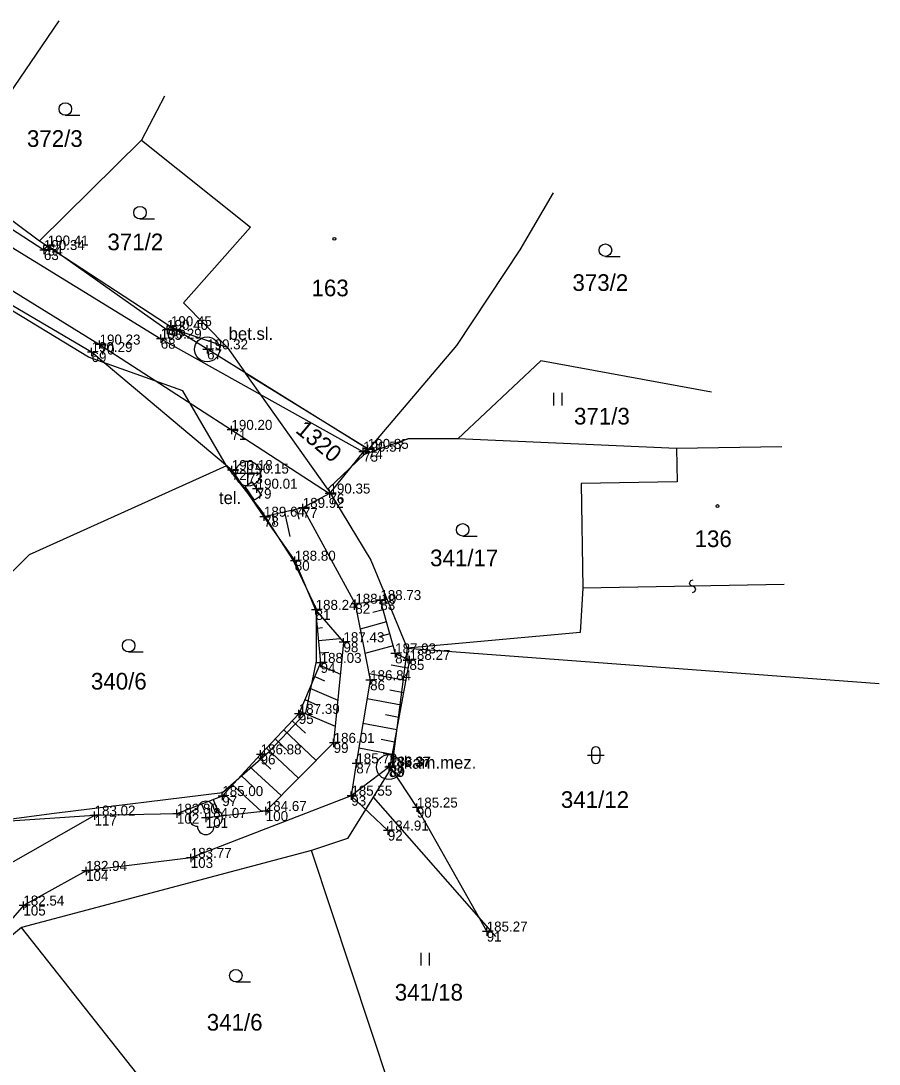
# Model space of a CAD drawing. Extents: x -744860 to -744734, y -966759 to -966608.
# Drawn here: x -744785.6 to -744734.1, y -966693.6 to -966631 of the extents above; entities that cross this region are included whole.
import ezdxf

# ---------------------------------------------------------------- set-up
doc = ezdxf.new("R2010")
doc.units = 0
for name, color, linetype in [('Bod polohopisu - výška', 7, 'Continuous'), ('Bod polohopisu - značka', 7, 'Continuous'), ('Bod polohopisu - číslo', 7, 'Continuous'), ('Doplňkové značky', 7, 'Continuous'), ('KM', 7, 'Continuous'), ('Ploty_opěrné zdi', 7, 'Continuous'), ('Popisy objektů_povrchů', 7, 'Continuous'), ('Rozhraní ploch', 7, 'Continuous'), ('Stromy_porost', 7, 'Continuous'), ('Vstup na pozemek', 7, 'Continuous'), ('Výškopis', 7, 'Continuous'), ('Značky IS', 7, 'Continuous')]:
    doc.layers.add(name, color=color, linetype=linetype)

msp = doc.modelspace()

# ---------------------------------------------------------------- linework, layer by layer
at = {"layer": 'Bod polohopisu - značka'}
for p, q in [((-744783.99, -966644.45), (-744784.24, -966644.45)), ((-744784.22, -966644.72), (-744784.22, -966644.47)), ((-744783.99, -966644.45), (-744783.99, -966644.2)), ((-744783.99, -966644.45), (-744783.74, -966644.45)), ((-744783.99, -966644.45), (-744783.99, -966644.7)), ((-744784.22, -966644.72), (-744784.47, -966644.72)), ((-744784.22, -966644.72), (-744783.97, -966644.72)), ((-744784.22, -966644.72), (-744784.22, -966644.97)), ((-744776.6, -966649.29), (-744776.85, -966649.29)), ((-744776.83, -966649.51), (-744776.83, -966649.26)), ((-744776.6, -966649.29), (-744776.6, -966649.04)), ((-744776.6, -966649.29), (-744776.35, -966649.29)), ((-744776.6, -966649.29), (-744776.6, -966649.54)), ((-744777.21, -966650.04), (-744777.46, -966650.04)), ((-744777.21, -966650.04), (-744777.21, -966649.79)), ((-744777.21, -966650.04), (-744776.96, -966650.04)), ((-744777.21, -966650.04), (-744777.21, -966650.29)), ((-744776.83, -966649.51), (-744777.08, -966649.51)), ((-744776.83, -966649.51), (-744776.58, -966649.51)), ((-744776.83, -966649.51), (-744776.83, -966649.76)), ((-744781.36, -966650.84), (-744781.36, -966650.59)), ((-744780.88, -966650.39), (-744781.13, -966650.39)), ((-744780.88, -966650.39), (-744780.88, -966650.14)), ((-744780.88, -966650.39), (-744780.63, -966650.39)), ((-744780.88, -966650.39), (-744780.88, -966650.64)), ((-744774.43, -966650.68), (-744774.68, -966650.68)), ((-744774.43, -966650.68), (-744774.43, -966650.43)), ((-744774.43, -966650.68), (-744774.18, -966650.68)), ((-744774.43, -966650.68), (-744774.43, -966650.93)), ((-744781.36, -966650.84), (-744781.61, -966650.84)), ((-744781.36, -966650.84), (-744781.11, -966650.84)), ((-744781.36, -966650.84), (-744781.36, -966651.09)), ((-744772.97, -966655.51), (-744773.22, -966655.51)), ((-744772.97, -966655.51), (-744772.97, -966655.26)), ((-744772.97, -966655.51), (-744772.72, -966655.51)), ((-744772.97, -966655.51), (-744772.97, -966655.76)), ((-744765.07, -966656.82), (-744765.32, -966656.82)), ((-744765.07, -966656.82), (-744765.07, -966656.57)), ((-744765.07, -966656.82), (-744764.82, -966656.82)), ((-744765.07, -966656.82), (-744765.07, -966657.07)), ((-744764.79, -966656.65), (-744765.04, -966656.65)), ((-744764.79, -966656.65), (-744764.79, -966656.4)), ((-744764.79, -966656.65), (-744764.54, -966656.65)), ((-744764.79, -966656.65), (-744764.79, -966656.9)), ((-744772.95, -966657.92), (-744773.2, -966657.92)), ((-744772.95, -966657.92), (-744772.95, -966657.67)), ((-744772.95, -966657.92), (-744772.7, -966657.92)), ((-744772.95, -966657.92), (-744772.95, -966658.17)), ((-744771.98, -966658.13), (-744772.23, -966658.13)), ((-744771.98, -966658.13), (-744771.98, -966657.88)), ((-744771.98, -966658.13), (-744771.73, -966658.13)), ((-744771.98, -966658.13), (-744771.98, -966658.38)), ((-744771.46, -966659.04), (-744771.46, -966658.79)), ((-744771.46, -966659.04), (-744771.71, -966659.04)), ((-744771.46, -966659.04), (-744771.21, -966659.04)), ((-744771.46, -966659.04), (-744771.46, -966659.29)), ((-744767.09, -966659.33), (-744767.34, -966659.33)), ((-744767.09, -966659.33), (-744767.09, -966659.08)), ((-744767.09, -966659.33), (-744766.84, -966659.33)), ((-744767.09, -966659.33), (-744767.09, -966659.58)), ((-744768.69, -966660.19), (-744768.69, -966659.94)), ((-744771.02, -966660.72), (-744771.27, -966660.72)), ((-744771.02, -966660.72), (-744771.02, -966660.47)), ((-744771.02, -966660.72), (-744770.77, -966660.72)), ((-744771.02, -966660.72), (-744771.02, -966660.97)), ((-744768.69, -966660.19), (-744768.94, -966660.19)), ((-744768.69, -966660.19), (-744768.44, -966660.19)), ((-744768.69, -966660.19), (-744768.69, -966660.44)), ((-744769.17, -966663.36), (-744769.17, -966663.11)), ((-744769.17, -966663.36), (-744769.42, -966663.36)), ((-744769.17, -966663.36), (-744768.92, -966663.36)), ((-744769.17, -966663.36), (-744769.17, -966663.61)), ((-744765.54, -966665.94), (-744765.54, -966665.69)), ((-744764.04, -966665.72), (-744764.29, -966665.72)), ((-744764.04, -966665.72), (-744764.04, -966665.47)), ((-744764.04, -966665.72), (-744763.79, -966665.72)), ((-744764.04, -966665.72), (-744764.04, -966665.97)), ((-744767.92, -966666.31), (-744768.17, -966666.31)), ((-744767.92, -966666.31), (-744767.92, -966666.06)), ((-744767.92, -966666.31), (-744767.67, -966666.31)), ((-744767.92, -966666.31), (-744767.92, -966666.56)), ((-744765.54, -966665.94), (-744765.79, -966665.94)), ((-744765.54, -966665.94), (-744765.29, -966665.94)), ((-744765.54, -966665.94), (-744765.54, -966666.19)), ((-744766.25, -966668.25), (-744766.5, -966668.25)), ((-744766.25, -966668.25), (-744766.25, -966668)), ((-744766.25, -966668.25), (-744766, -966668.25)), ((-744766.25, -966668.25), (-744766.25, -966668.5)), ((-744763.15, -966668.92), (-744763.15, -966668.67)), ((-744767.62, -966669.49), (-744767.87, -966669.49)), ((-744767.62, -966669.49), (-744767.62, -966669.24)), ((-744767.62, -966669.49), (-744767.37, -966669.49)), ((-744767.62, -966669.49), (-744767.62, -966669.74)), ((-744763.15, -966668.92), (-744763.4, -966668.92)), ((-744763.15, -966668.92), (-744762.9, -966668.92)), ((-744763.15, -966668.92), (-744763.15, -966669.17)), ((-744762.29, -966669.31), (-744762.54, -966669.31)), ((-744762.29, -966669.31), (-744762.29, -966669.06)), ((-744762.29, -966669.31), (-744762.04, -966669.31)), ((-744762.29, -966669.31), (-744762.29, -966669.56)), ((-744764.65, -966670.53), (-744764.9, -966670.53)), ((-744764.65, -966670.53), (-744764.65, -966670.28)), ((-744764.65, -966670.53), (-744764.4, -966670.53)), ((-744764.65, -966670.53), (-744764.65, -966670.78)), ((-744768.93, -966672.55), (-744769.18, -966672.55)), ((-744768.93, -966672.55), (-744768.93, -966672.3)), ((-744768.93, -966672.55), (-744768.68, -966672.55)), ((-744768.93, -966672.55), (-744768.93, -966672.8)), ((-744766.84, -966674.29), (-744767.09, -966674.29)), ((-744766.84, -966674.29), (-744766.84, -966674.04)), ((-744766.84, -966674.29), (-744766.59, -966674.29)), ((-744766.84, -966674.29), (-744766.84, -966674.54)), ((-744771.22, -966674.98), (-744771.47, -966674.98)), ((-744771.22, -966674.98), (-744771.22, -966674.73)), ((-744771.22, -966674.98), (-744770.97, -966674.98)), ((-744771.22, -966674.98), (-744771.22, -966675.23)), ((-744765.48, -966675.52), (-744765.73, -966675.52)), ((-744765.48, -966675.52), (-744765.48, -966675.27)), ((-744765.48, -966675.52), (-744765.23, -966675.52)), ((-744765.48, -966675.52), (-744765.48, -966675.77)), ((-744763.52, -966675.74), (-744763.77, -966675.74)), ((-744763.46, -966675.71), (-744763.71, -966675.71)), ((-744763.52, -966675.74), (-744763.52, -966675.49)), ((-744763.52, -966675.74), (-744763.27, -966675.74)), ((-744763.52, -966675.74), (-744763.52, -966675.99)), ((-744763.46, -966675.71), (-744763.46, -966675.46)), ((-744763.46, -966675.71), (-744763.21, -966675.71)), ((-744763.46, -966675.71), (-744763.46, -966675.96)), ((-744773.52, -966677.48), (-744773.77, -966677.48)), ((-744773.52, -966677.48), (-744773.52, -966677.23)), ((-744773.52, -966677.48), (-744773.27, -966677.48)), ((-744773.52, -966677.48), (-744773.52, -966677.73)), ((-744765.78, -966677.46), (-744766.03, -966677.46)), ((-744765.78, -966677.46), (-744765.78, -966677.21)), ((-744765.78, -966677.46), (-744765.53, -966677.46)), ((-744765.78, -966677.46), (-744765.78, -966677.71)), ((-744770.91, -966678.38), (-744770.91, -966678.13)), ((-744761.85, -966678.17), (-744762.1, -966678.17)), ((-744761.85, -966678.17), (-744761.85, -966677.92)), ((-744761.85, -966678.17), (-744761.6, -966678.17)), ((-744761.85, -966678.17), (-744761.85, -966678.42)), ((-744781.18, -966678.65), (-744781.43, -966678.65)), ((-744781.18, -966678.65), (-744781.18, -966678.4)), ((-744781.18, -966678.65), (-744780.93, -966678.65)), ((-744781.18, -966678.65), (-744781.18, -966678.9)), ((-744776.24, -966678.54), (-744776.49, -966678.54)), ((-744776.24, -966678.54), (-744776.24, -966678.29)), ((-744776.24, -966678.54), (-744775.99, -966678.54)), ((-744776.24, -966678.54), (-744776.24, -966678.79)), ((-744774.51, -966678.79), (-744774.76, -966678.79)), ((-744774.51, -966678.79), (-744774.51, -966678.54)), ((-744774.51, -966678.79), (-744774.26, -966678.79)), ((-744774.51, -966678.79), (-744774.51, -966679.04)), ((-744770.91, -966678.38), (-744771.16, -966678.38)), ((-744770.91, -966678.38), (-744770.66, -966678.38)), ((-744770.91, -966678.38), (-744770.91, -966678.63)), ((-744763.59, -966679.55), (-744763.59, -966679.3)), ((-744763.59, -966679.55), (-744763.84, -966679.55)), ((-744763.59, -966679.55), (-744763.34, -966679.55)), ((-744763.59, -966679.55), (-744763.59, -966679.8)), ((-744775.41, -966681.19), (-744775.66, -966681.19)), ((-744775.41, -966681.19), (-744775.41, -966680.94)), ((-744775.41, -966681.19), (-744775.16, -966681.19)), ((-744775.41, -966681.19), (-744775.41, -966681.44)), ((-744781.69, -966681.97), (-744781.94, -966681.97)), ((-744781.69, -966681.97), (-744781.69, -966681.72)), ((-744781.69, -966681.97), (-744781.44, -966681.97)), ((-744781.69, -966681.97), (-744781.69, -966682.22)), ((-744785.45, -966684.05), (-744785.45, -966683.8)), ((-744785.45, -966684.05), (-744785.7, -966684.05)), ((-744785.45, -966684.05), (-744785.2, -966684.05)), ((-744785.45, -966684.05), (-744785.45, -966684.3)), ((-744757.66, -966685.61), (-744757.91, -966685.61)), ((-744757.66, -966685.61), (-744757.66, -966685.36)), ((-744757.66, -966685.61), (-744757.41, -966685.61)), ((-744757.66, -966685.61), (-744757.66, -966685.86))]:
    msp.add_line(p, q, dxfattribs=at)
at = {"layer": 'Doplňkové značky'}
for centre in [(-744774.43, -966650.68), (-744763.52, -966675.74)]:
    msp.add_circle(centre, 0.75, dxfattribs=at)
at = {"layer": 'KM'}
for p, q in [((-744789.67, -966640.3), (-744783.3, -966630.97)), ((-744782.937, -966636.63), (-744782.062, -966636.63)), ((-744778.37, -966638.12), (-744784.48, -966644.17)), ((-744789.67, -966640.3), (-744784.48, -966644.17)), ((-744778.456, -966642.85), (-744777.581, -966642.85)), ((-744750.538, -966645.102), (-744749.663, -966645.102)), ((-744781.55, -966651.15), (-744788.18, -966647.11)), ((-744773.22, -966650.55), (-744772.12, -966652.1)), ((-744764.73, -966656.66), (-744759.45, -966650.45)), ((-744754.42, -966651.36), (-744759.4, -966656.05)), ((-744744.18, -966653.24), (-744754.42, -966651.36)), ((-744767.18, -966659.06), (-744772.12, -966652.1)), ((-744772.12, -966652.1), (-744764.73, -966656.66)), ((-744753.635, -966654.047), (-744753.635, -966653.297)), ((-744753.135, -966654.047), (-744753.135, -966653.297)), ((-744746.27, -966656.63), (-744759.4, -966656.05)), ((-744765.01, -966656.99), (-744767.18, -966659.06)), ((-744764.73, -966656.66), (-744765.01, -966656.99)), ((-744759.096, -966661.88), (-744758.221, -966661.88)), ((-744739.809, -966664.794), (-744751.89, -966665)), ((-744779.137, -966668.83), (-744778.262, -966668.83)), ((-744762.42, -966668.6), (-744734.12, -966670.73)), ((-744751.613, -966675.017), (-744750.612, -966675.017)), ((-744751.363, -966674.767), (-744751.363, -966675.267)), ((-744750.862, -966675.267), (-744750.862, -966674.767)), ((-744764.47, -966677.55), (-744757.14, -966685.91)), ((-744768.17, -966680.74), (-744785.56, -966685.37)), ((-744760.83, -966702.86), (-744768.17, -966680.74)), ((-744771, -966703.8), (-744785.56, -966685.37)), ((-744761.594, -966687.637), (-744761.594, -966686.887)), ((-744761.093, -966687.637), (-744761.093, -966686.887)), ((-744772.707, -966688.628), (-744771.832, -966688.628))]:
    msp.add_line(p, q, dxfattribs=at)
for points in [[(-744776.99, -966635.48), (-744778.37, -966638.12)], [(-744778.37, -966638.12), (-744771.83, -966643.35), (-744775.85, -966647.89), (-744773.22, -966650.55)], [(-744759.45, -966650.45), (-744755.66, -966644.71), (-744753.65, -966641.28)], [(-744784.48, -966644.17), (-744776.34, -966649.49), (-744773.22, -966650.55)], [(-744773.26, -966657.67), (-744775.88, -966653.17), (-744781.55, -966651.15)], [(-744759.4, -966656.05), (-744762.36, -966656.04), (-744765.01, -966656.99)], [(-744746.27, -966656.63), (-744746.23, -966658.62), (-744752, -966658.72), (-744751.89, -966665), (-744752.05, -966667.67), (-744762.42, -966668.6)], [(-744739.95, -966656.52), (-744746.27, -966656.63)], [(-744773.26, -966657.67), (-744785.1, -966663), (-744789.495, -966667.418)], [(-744787.69, -966679.04), (-744783.61, -966678.5), (-744773.51, -966677.27), (-744770.7, -966674.8), (-744768.5, -966672.49), (-744767.87, -966669.38), (-744767.86, -966666.26), (-744769.28, -966663.29), (-744771.19, -966660.32), (-744773.26, -966657.67)], [(-744767.18, -966659.06), (-744764.6, -966663.33), (-744762.42, -966668.6)], [(-744745.319, -966665.263), (-744745.17, -966665.211), (-744745.113, -966665.055), (-744745.185, -966664.921), (-744745.427, -966664.84), (-744745.489, -966664.701), (-744745.422, -966664.555), (-744745.282, -966664.512)], [(-744762.42, -966668.6), (-744763.34, -966675.72), (-744764.47, -966677.55)], [(-744764.47, -966677.55), (-744766, -966680.03), (-744768.17, -966680.74)], [(-744785.56, -966685.37), (-744792.95, -966691.5), (-744798.91, -966697.31)]]:
    msp.add_lwpolyline(points, dxfattribs=at)
for centre, radius in [((-744782.936, -966636.255), 0.375), ((-744778.456, -966642.475), 0.375), ((-744766.793, -966644.045), 0.0875), ((-744750.538, -966644.727), 0.375), ((-744743.816, -966660.08), 0.0875), ((-744759.096, -966661.505), 0.375), ((-744779.136, -966668.455), 0.375), ((-744772.707, -966688.253), 0.375)]:
    msp.add_circle(centre, radius, dxfattribs=at)
for centre, start, end in [((-744751.113, -966674.767), 0, 180), ((-744751.113, -966675.267), 180, 359.98789)]:
    msp.add_arc(centre, 0.25, start, end, dxfattribs=at)
at = {"layer": 'Ploty_opěrné zdi'}
for points in [[(-744784.22, -966644.72), (-744789.39, -966641.39), (-744797.95, -966635.69)], [(-744784.22, -966644.72), (-744783.99, -966644.45), (-744776.83, -966649.51), (-744776.6, -966649.29), (-744764.79, -966656.65)], [(-744772.95, -966657.92), (-744781.36, -966650.84), (-744791.49, -966644.91)], [(-744764.79, -966656.65), (-744765.07, -966656.82)], [(-744772.95, -966657.92), (-744771.02, -966660.72), (-744769.17, -966663.36), (-744767.92, -966666.31), (-744767.62, -966669.49), (-744768.93, -966672.55), (-744771.22, -966674.98), (-744773.52, -966677.48), (-744776.24, -966678.54)], [(-744767.09, -966659.33), (-744768.69, -966660.19), (-744765.54, -966665.94), (-744764.04, -966665.72)], [(-744764.04, -966665.72), (-744763.15, -966668.92), (-744762.29, -966669.31)], [(-744762.29, -966669.31), (-744763.46, -966675.71), (-744761.85, -966678.17)], [(-744761.85, -966678.17), (-744757.66, -966685.61)], [(-744776.24, -966678.54), (-744781.18, -966678.65), (-744788.06, -966679.1), (-744794.89, -966683.71)]]:
    msp.add_lwpolyline(points, dxfattribs=at)
at = {"layer": 'Rozhraní ploch'}
for points in [[(-744807.21, -966636.7), (-744806.82, -966636.25), (-744799.04, -966639.39), (-744791.03, -966644.12), (-744780.88, -966650.39), (-744772.97, -966655.51), (-744767.09, -966659.33)], [(-744796.67, -966637.96), (-744789.94, -966642.23), (-744777.21, -966650.04), (-744765.07, -966656.82)]]:
    msp.add_lwpolyline(points, dxfattribs=at)
at = {"layer": 'Stromy_porost'}
for points in [[(-744763.59, -966679.55), (-744765.78, -966677.46), (-744775.41, -966681.19), (-744781.69, -966681.97), (-744785.45, -966684.05), (-744788.92, -966688.06), (-744792.9, -966691.9), (-744797.56, -966696.54), (-744801.48, -966702.05), (-744809.76, -966709.76), (-744814.1, -966714.28), (-744821.74, -966720.14), (-744827.24, -966731.82), (-744829.32, -966738.32), (-744831.32, -966741.72), (-744834.98, -966747.08), (-744831.81, -966750.81), (-744822.41, -966749.82)], [(-744781.18, -966678.65), (-744792.93, -966685.32), (-744796.85, -966689.7), (-744800.79, -966697.66), (-744807.35, -966700.35), (-744816.47, -966709.2)]]:
    msp.add_lwpolyline(points, dxfattribs=at)
msp.add_circle((-744774.51, -966678.79), 0.0005, dxfattribs=at)
for centre, start, end in [((-744774.51, -966678.29), 0, 179.99999), ((-744775.01, -966678.79), 89.99999, 269.99999), ((-744774.01, -966678.79), 270, 89.99999), ((-744774.51, -966679.29), 179.99999, 359.99999)]:
    msp.add_arc(centre, 0.5, start, end, dxfattribs=at)
at = {"layer": 'Vstup na pozemek'}
msp.add_lwpolyline([(-744765.07, -966656.82), (-744767.09, -966659.33)], dxfattribs=at)
at = {"layer": 'Výškopis'}
for points in [[(-744768.69, -966660.19), (-744771.02, -966660.72)], [(-744770.523, -966660.607), (-744770.39, -966661.192)], [(-744769.792, -966660.441), (-744769.459, -966661.903)], [(-744769.061, -966660.274), (-744768.927, -966660.859)], [(-744767.92, -966666.31), (-744766.25, -966668.25), (-744766.84, -966674.29), (-744770.91, -966678.38), (-744774.51, -966678.79)], [(-744765.54, -966665.94), (-744764.65, -966670.53), (-744765.48, -966675.52), (-744765.78, -966677.46)], [(-744763.879, -966666.299), (-744764.483, -966666.467)], [(-744767.817, -966667.398), (-744767.509, -966667.369)], [(-744763.678, -966667.022), (-744765.246, -966667.458)], [(-744767.747, -966668.145), (-744766.446, -966668.022)], [(-744763.477, -966667.744), (-744764.127, -966667.925)], [(-744767.676, -966668.891), (-744767.126, -966668.839)], [(-744763.276, -966668.467), (-744764.959, -966668.935)], [(-744767.678, -966669.627), (-744766.436, -966670.158)], [(-744762.382, -966669.812), (-744763.38, -966669.629)], [(-744767.974, -966670.316), (-744767.389, -966670.566)], [(-744762.517, -966670.549), (-744764.724, -966670.146)], [(-744768.269, -966671.006), (-744766.589, -966671.725)], [(-744762.651, -966671.287), (-744763.476, -966671.136)], [(-744768.564, -966671.695), (-744767.805, -966672.02)], [(-744762.786, -966672.025), (-744764.836, -966671.65)], [(-744768.859, -966672.384), (-744766.742, -966673.291)], [(-744762.921, -966672.763), (-744763.736, -966672.614)], [(-744769.321, -966672.965), (-744768.537, -966673.704)], [(-744763.056, -966673.501), (-744765.082, -966673.13)], [(-744769.835, -966673.511), (-744767.889, -966675.344)], [(-744770.35, -966674.056), (-744769.577, -966674.784)], [(-744763.191, -966674.238), (-744763.997, -966674.091)], [(-744770.864, -966674.602), (-744768.948, -966676.408)], [(-744763.326, -966674.976), (-744765.329, -966674.61)], [(-744771.884, -966675.702), (-744769.984, -966677.45)], [(-744771.376, -966675.15), (-744770.608, -966675.857)], [(-744763.46, -966675.71), (-744765.78, -966677.46)], [(-744772.392, -966676.254), (-744771.641, -966676.945)], [(-744772.9, -966676.806), (-744771.158, -966678.408)], [(-744773.408, -966677.358), (-744772.902, -966677.823)], [(-744774.763, -966677.964), (-744774.635, -966678.292)], [(-744774.064, -966677.692), (-744773.673, -966678.695)]]:
    msp.add_lwpolyline(points, dxfattribs=at)
at = {"layer": 'Značky IS'}
for p, q in [((-744771.981, -966658.878), (-744771.98, -966657.383)), ((-744771.228, -966658.136), (-744772.728, -966658.131))]:
    msp.add_line(p, q, dxfattribs=at)
msp.add_lwpolyline([(-744771.176, -966659.452), (-744771.588, -966659.735), (-744772.155, -966658.912), (-744771.744, -966658.628)], close=True, dxfattribs=at)
msp.add_circle((-744771.98, -966658.13), 0.75, dxfattribs=at)

# ---------------------------------------------------------------- texts
at = {"layer": 'Bod polohopisu - výška'}
for s, p in [('190.41', (-744783.99, -966644.45)), ('190.34', (-744784.22, -966644.72)), ('190.45', (-744776.6, -966649.29)), ('190.29', (-744777.21, -966650.04)), ('190.40', (-744776.83, -966649.51)), ('190.23', (-744780.88, -966650.39)), ('190.32', (-744774.43, -966650.68)), ('190.29', (-744781.36, -966650.84)), ('190.20', (-744772.97, -966655.51)), ('190.57', (-744765.07, -966656.82)), ('190.85', (-744764.79, -966656.65)), ('190.18', (-744772.95, -966657.92)), ('190.15', (-744771.98, -966658.13)), ('190.01', (-744771.46, -966659.04)), ('190.35', (-744767.09, -966659.33)), ('189.64', (-744771.02, -966660.72)), ('189.92', (-744768.69, -966660.19)), ('188.80', (-744769.17, -966663.36)), ('188.73', (-744764.04, -966665.72)), ('188.24', (-744767.92, -966666.31)), ('188.10', (-744765.54, -966665.94)), ('187.43', (-744766.25, -966668.25)), ('188.03', (-744767.62, -966669.49)), ('187.93', (-744763.15, -966668.92)), ('188.27', (-744762.29, -966669.31)), ('186.84', (-744764.65, -966670.53)), ('187.39', (-744768.93, -966672.55)), ('186.01', (-744766.84, -966674.29)), ('186.88', (-744771.22, -966674.98)), ('185.79', (-744765.48, -966675.52)), ('186.37', (-744763.52, -966675.74)), ('186.37', (-744763.46, -966675.71)), ('185.00', (-744773.52, -966677.48)), ('185.55', (-744765.78, -966677.46)), ('185.25', (-744761.85, -966678.17)), ('183.02', (-744781.18, -966678.65)), ('183.80', (-744776.24, -966678.54)), ('184.07', (-744774.51, -966678.79)), ('184.67', (-744770.91, -966678.38)), ('184.91', (-744763.59, -966679.55)), ('183.77', (-744775.41, -966681.19)), ('182.94', (-744781.69, -966681.97)), ('182.54', (-744785.45, -966684.05)), ('185.27', (-744757.66, -966685.61))]:
    msp.add_text(s, height=0.6, dxfattribs=at).set_placement(p)
at = {"layer": 'Bod polohopisu - číslo'}
for s, p in [('64', (-744783.99, -966645.05)), ('63', (-744784.22, -966645.32)), ('66', (-744776.6, -966649.89)), ('68', (-744777.21, -966650.64)), ('65', (-744776.83, -966650.11)), ('70', (-744780.88, -966650.99)), ('67', (-744774.43, -966651.28)), ('69', (-744781.36, -966651.44)), ('71', (-744772.97, -966656.11)), ('75', (-744765.07, -966657.42)), ('74', (-744764.79, -966657.25)), ('72', (-744772.95, -966658.52)), ('73', (-744771.98, -966658.73)), ('79', (-744771.46, -966659.64)), ('76', (-744767.09, -966659.93)), ('78', (-744771.02, -966661.32)), ('77', (-744768.69, -966660.79)), ('80', (-744769.17, -966663.96)), ('83', (-744764.04, -966666.32)), ('81', (-744767.92, -966666.91)), ('82', (-744765.54, -966666.54)), ('98', (-744766.25, -966668.85)), ('94', (-744767.62, -966670.09)), ('84', (-744763.15, -966669.52)), ('85', (-744762.29, -966669.91)), ('86', (-744764.65, -966671.13)), ('95', (-744768.93, -966673.15)), ('99', (-744766.84, -966674.89)), ('96', (-744771.22, -966675.58)), ('87', (-744765.48, -966676.12)), ('88', (-744763.52, -966676.34)), ('89', (-744763.46, -966676.31)), ('97', (-744773.52, -966678.08)), ('93', (-744765.78, -966678.06)), ('90', (-744761.85, -966678.77)), ('117', (-744781.18, -966679.25)), ('102', (-744776.24, -966679.14)), ('101', (-744774.51, -966679.39)), ('100', (-744770.91, -966678.98)), ('92', (-744763.59, -966680.15)), ('103', (-744775.41, -966681.79)), ('104', (-744781.69, -966682.57)), ('105', (-744785.45, -966684.65)), ('91', (-744757.66, -966686.21))]:
    msp.add_text(s, height=0.6, dxfattribs=at).set_placement(p)
at = {"layer": 'KM'}
for s, p in [('372/3', (-744785.237, -966638.531)), ('371/2', (-744780.407, -966644.732)), ('373/2', (-744752.516, -966647.171)), ('163', (-744768.167, -966647.495)), ('371/3', (-744752.421, -966655.187)), ('136', (-744745.189, -966662.541)), ('341/17', (-744761.055, -966663.691)), ('340/6', (-744781.398, -966671.089)), ('341/12', (-744753.211, -966678.191)), ('341/18', (-744763.173, -966689.753)), ('341/6', (-744774.45, -966691.551))]:
    msp.add_text(s, height=1, dxfattribs=at).set_placement(p)
msp.add_text('1320', height=1, rotation=320, dxfattribs=at).set_placement((-744769.179, -966655.617))
at = {"layer": 'Popisy objektů_povrchů'}
for s, p in [('bet.sl.', (-744773.14, -966650.11)), ('tel.', (-744773.72, -966659.96)), ('kam.mez.', (-744762.63, -966675.84))]:
    msp.add_text(s, height=0.75, dxfattribs=at).set_placement(p)

doc.saveas('drawing.dxf')
